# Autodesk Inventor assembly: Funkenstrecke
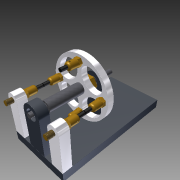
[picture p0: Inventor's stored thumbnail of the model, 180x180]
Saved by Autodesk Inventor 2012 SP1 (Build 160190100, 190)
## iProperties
Created: 2012-10
Part Number: Funkenstrecke
Document SubType Name: Assembly
Designer: Dominic Mähling
Author: Dominic Mähling
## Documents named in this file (14)
- D:\Dokumente\CAD\Funkenstrecke\Funkenstrecke.iam
- D:\Dokumente\CAD\Funkenstrecke\Bodenplatte.ipt
- D:\Dokumente\CAD\Funkenstrecke\Elektrodenhalterung.ipt
- D:\Dokumente\CAD\Funkenstrecke\Lagerhalterung.ipt
- D:\Dokumente\CAD\Funkenstrecke\Elektrodeneinsatz.ipt
- D:\Dokumente\CAD\Funkenstrecke\Elektrode.ipt
- D:\Dokumente\CAD\Funkenstrecke\Welle.ipt
- D:\Dokumente\CAD\Funkenstrecke\Scheibe.ipt
- D:\Dokumente\CAD\Funkenstrecke\Mutter.ipt
- D:\Dokumente\CAD\Funkenstrecke\Elektrodeneinsatz rot.ipt
- D:\Dokumente\CAD\Funkenstrecke\Elektrode rot.ipt
- D:\Dokumente\CAD\Funkenstrecke\Elektrodenhalterung_MIR.ipt
- D:\Dokumente\CAD\Funkenstrecke\Elektrodeneinsatz_MIR.ipt
- D:\Dokumente\CAD\Funkenstrecke\Elektrode_MIR.ipt
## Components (20 placed, 13 different names)
1. Bodenplatte:1 — Passend:1, Passend:2, Passend:3
2. Elektrodenhalterung:1
3. Lagerhalterung:1
4. Elektrodeneinsatz:1
5. Elektrode:1
6. Welle:1
7. Scheibe:1
8. Mutter:1
9. Elektrodenhalterung_MIR:1
10. Elektrodeneinsatz_MIR:1
11. Elektrode_MIR:1
12. Lagerhalterung:2 — Passend:1, Passend:2, Passend:3
13. Elektrodeneinsatz rot:1
14. Elektrodeneinsatz rot:2
15. Elektrodeneinsatz rot:3
16. Elektrodeneinsatz rot:4
17. Elektrode rot:1
18. Elektrode rot:2
19. Elektrode rot:3
20. Elektrode rot:4
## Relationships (3: Mate 3)
- Passend:1 [Mate]: Bodenplatte:1 ↔ Lagerhalterung:2
- Passend:2 [Mate]: Bodenplatte:1 ↔ Lagerhalterung:2
- Passend:3 [Mate]: Bodenplatte:1 ↔ Lagerhalterung:2
